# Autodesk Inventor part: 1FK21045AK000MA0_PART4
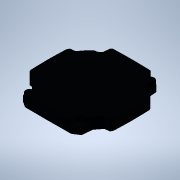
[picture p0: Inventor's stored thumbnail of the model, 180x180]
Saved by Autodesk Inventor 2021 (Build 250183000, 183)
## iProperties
Created: 2025-04
Part Number: 1FK21045AK000MA0_PART4
Material: Generic
Catalog Web Link: www.3dfindit.com
Description: -Servo synchronous motor
Document SubType Name: Modeling
Designer: psAdmin
Mass: 55.5405 g
Surface Area: 149.572 cm^2
Volume: 55.5405 cm^3
Density: 1 g/cm^3
Appearance: PSOLRGB-38-46-56
Category: PARTsolutions
Title: 1FK21045AK000MA0_PART4
Author: Cadenas PARTsolutions
Comments: Servo synchronous motor
Sending System: PARTsolutions
Preprocessor: ST-DEVELOPER v19.3
PSOL_IDENT_0: {$CADENAS_DATA/23d-libs/siemens_ag/_cat_/3d/2f/1fk21045ak000ma0.prj},213 {VTYP=3D},{NB=1FK21045AK000
PSOL_IDENT_1: MA0_PART4},{LINA=1FK21045AK000MA0_PART4},{NN=1FK21045AK000MA0_PART4},{NOPRJ=TRUE},{DATE=19.08.2025 1
PSOL_IDENT_2: 4:00:34},{GEOMDATE=30.07.2025 02:01:24},{VERSION=},{LINEID=10},{WBVAR=},{WBNUMERIC=}  {NB=1FK21045AK
PSOL_IDENT_3: 000MA0_PART4},{LINA=1FK21045AK000MA0_PART4},{KT=DUMMY},{PREVIEW=../../../_pool_/a9/69/p_d211_xx_0081
PSOL_IDENT_4: 8j.png},{DESCSHORT=SIMOTICS S-1FK2 HD, SINAMICS S210 3AC 400V-480V, 1.7 Nm, 6000 rpm},{DESCLONG=SIMO
PSOL_IDENT_5: TICS S-1FK2 HD servo motor M0=2.4 Nm; PN = 1.07 kW at nN=6000 rpm (380-480 V); PN = 0.75 kW at nN=30
PSOL_IDENT_6: 00 rpm (200-240 V); degree of protection IP64; cylindrical shaft D19x40mm; absolute encoder 22-bit +
PSOL_IDENT_7: 12-bit multiturn (encoder AM22DQC); with OCC interface; plug size M17, rotatable; SIMOTICS S-1FK2 s
PSOL_IDENT_8: ervomotorfor a wide range of uses in industrial environments. SIMOTICS S‑1FK2 servomotors are compac
PSOL_IDENT_9: t synchronous motors with a high dynamic performance that set themselves apart as a result of their
PSOL_IDENT_10: high power density, degree of protection and overload capability. The motors are available in two va
PSOL_IDENT_11: riants: as High Dynamic variant (highest dynamic performance as a result of the low intrinsic moment
PSOL_IDENT_12: of inertia for applications demanding a high dynamic performance with low moved masses) - and as Co
PSOL_IDENT_13: mpact variant (precise and stable closed-loop control for medium up to large moved masses as a resul
PSOL_IDENT_14: t of a medium intrinsic moment of inertia). SIMOTICSS‑1FK2 servomotors fully exploit their strengths
PSOL_IDENT_15: in a system with the SINAMICSS210 frequency converter and simple connection using the one cable con
PSOL_IDENT_16: nection (OCC). Advantages include the short control and positioning times, fast and precise correcti
PSOL_IDENT_17: on of disturbing quantities as well as stable control with a high dynamic performance. The servo mot
PSOL_IDENT_18: ors can be configured to address a wide range of requirements. For example with and without holding
PSOL_IDENT_19: brake, IP64 or IP65 degree of protection, singleturn or multiturn absolute encoders - to name just a
PSOL_IDENT_20: few. Further, the servomotors are available in different shaft heights extending from 20 to 100. A
PSOL_IDENT_21: shaft sealing ring is available to achieve an IP65 degree of protection and for subsequent mounting
PSOL_IDENT_22: at the motor or as spare part. SIMOTICS - the optimum motor for each and every motion control applic
PSOL_IDENT_23: ation.},{INTNO=804766789342},{SUPPLIERALTNO=1FK2104-5AK00-0MA0},{MANUID=1FK21045AK000MA0},{MANUNAME=
PSOL_IDENT_24: Siemens},{MANUTYPEDESC=Synchronous motor 1FK2-HD 2,39 Nm},{AAU732=SIMOTICS},{AAO057=S-1FK2},{AAU734=
PSOL_IDENT_25: SIMOTICS S-1FK2 HD servo motor M0=2.4 Nm; PN = 1.07 kW at nN=6000 rpm (380-480 V); PN = 0.75 kW at n
PSOL_IDENT_26: N=3000 rpm (200-240 V); degree of protection IP64; cylindrical shaft D19x40mm; absolute encoder 22-b
PSOL_IDENT_27: it + 12-bit multiturn (encoder AM22DQC); with OCC interface; plug size M17, rotatable;},{AAW338=Sync
PSOL_IDENT_28: hronous motor 1FK2-HD 2,39 Nm},{AAO742=SIMOTICS},{AAO663=4042948691151},{NOCUPEROU=1},{PRICEQUANTITY=
PSOL_IDENT_29: 1},{QUANTITYMIN=1},{QUANTITYINT=1},{CTN=85015100},{COO=DE},{AAO676=1FK2104-5AK00-0MA0},{AAO677=Sieme
PSOL_IDENT_30: ns AG},{ORDERUNIT=C62},{CONTENTUNIT=C62}
NB: 1FK21045AK000MA0_PART4
NT: Servo synchronous motor
NBSYN: $MANUID._PART4
LINA: 1FK21045AK000MA0_PART4
CATALOG: SIEMENS
PREVIEW: ../../../_pool_/a9/69/p_d211_xx_00818j.png
DESCSHORT: SIMOTICS S-1FK2 HD, SINAMICS S210 3AC 400V-480V, 1.7 Nm, 6000 rpm
DESCLONG: SIMOTICS S-1FK2 HD servo motor M0=2.4 Nm; PN = 1.07 kW at nN=6000 rpm (380-480 V); PN = 0.75 kW at nN=3000 rpm (200-240 V); degree of protection IP64; cylindric
INTNO: 804766789342
SUPPLIERALTNO: 1FK2104-5AK00-0MA0
MANUID: 1FK21045AK000MA0
MANUNAME: Siemens
MANUTYPEDESC: Synchronous motor 1FK2-HD 2,39 Nm
AAU732: SIMOTICS
AAO057: S-1FK2
AAU734: SIMOTICS S-1FK2 HD servo motor M0=2.4 Nm; PN = 1.07 kW at nN=6000 rpm (380-480 V); PN = 0.75 kW at nN=3000 rpm (200-240 V); degree of protection IP64; cylindric
AAW338: Synchronous motor 1FK2-HD 2,39 Nm
AAO742: SIMOTICS
AAO663: 4042948691151.0
NOCUPEROU: 1
PRICEQUANTITY: 1
QUANTITYMIN: 1
QUANTITYINT: 1
CTN: 85015100
COO: DE
ARTICLENO: 1FK21045AK000MA0_PART4
BOMINFO: 1FK21045AK000MA0_PART4
CREATOR: CADENAS GmbH
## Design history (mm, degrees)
feature "2025_04_17_15_39_51_0634"
body "Solid1"
